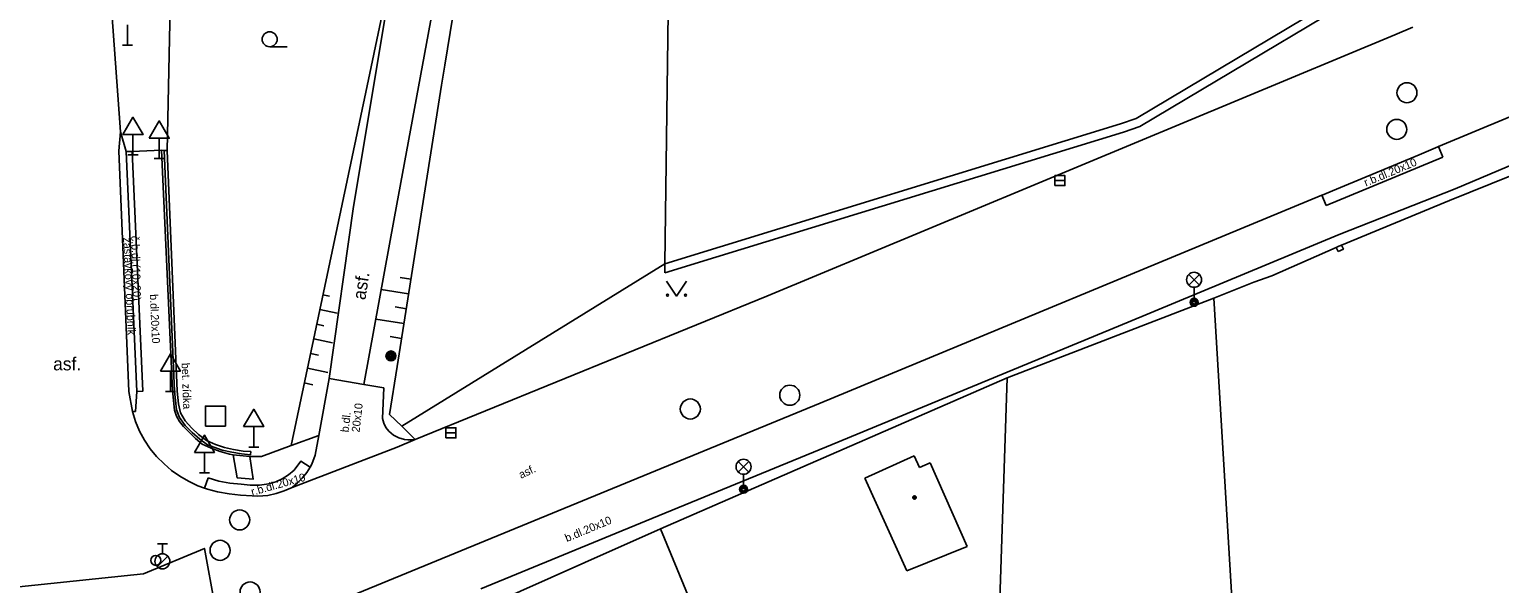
# Model space of a CAD drawing. Extents: x -598233 to -596890, y -1157848 to -1156431.
# Drawn here: x -598021.4 to -597948, y -1157077.3 to -1157049.6 of the extents above; entities that cross this region are included whole.
import ezdxf

# ---------------------------------------------------------------- set-up
doc = ezdxf.new("R2010")
doc.units = 0
for name, color, linetype in [('Level 10', 7, 'Continuous'), ('Level 11', 7, 'Continuous'), ('Level 15', 7, 'Continuous'), ('Level 24', 7, 'Continuous'), ('Level 25', 7, 'Continuous'), ('Level 26', 7, 'Continuous'), ('Level 27', 7, 'Continuous'), ('Level 28', 7, 'Continuous'), ('Level 33', 7, 'Continuous'), ('Level 34', 7, 'Continuous'), ('Level 36', 7, 'Continuous'), ('Level 39', 7, 'Continuous'), ('Level 40', 7, 'Continuous'), ('Level 5', 7, 'Continuous'), ('Level 7', 7, 'Continuous'), ('Level 8', 7, 'Continuous'), ('Vrstva 54', 7, 'Continuous'), ('Vrstva 60', 7, 'Continuous')]:
    doc.layers.add(name, color=color, linetype=linetype)

msp = doc.modelspace()

# ---------------------------------------------------------------- linework, layer by layer
at = {"layer": 'Level 10'}
for points in [[(-597997.82, -1157011.45), (-597999.15, -1157022.95), (-598000.01, -1157041.65), (-598003.21, -1157058.99)], [(-598017.85, -1157035.59), (-598017.6, -1157045.12), (-598016.9, -1157054.74)], [(-597953.22, -1157049.89), (-597984.6, -1157062.95)], [(-597952.31, -1157049.51), (-597953.22, -1157049.89)], [(-597944.1, -1157052.59), (-597951.04, -1157055.48), (-597951.07, -1157055.49)], [(-598016.97, -1157055.69), (-598016.9, -1157054.74)], [(-598016.47, -1157067.72), (-598016.97, -1157055.69)], [(-597951.07, -1157055.49), (-597952, -1157055.89), (-597955.94, -1157057.52)], [(-597956.86, -1157057.91), (-597981.94, -1157068.3)], [(-597955.94, -1157057.52), (-597956.84, -1157057.9), (-597956.86, -1157057.91)], [(-598006.47, -1157067.07), (-598005.25, -1157058.48)], [(-598003.21, -1157058.99), (-598004.74, -1157067.36)], [(-597984.6, -1157062.95), (-598002.17, -1157070.12)], [(-598006.98, -1157069.91), (-598006.47, -1157067.07)], [(-598004.74, -1157067.36), (-598003.73, -1157067.53)], [(-598003.73, -1157067.53), (-598003.81, -1157069.07)], [(-598016.29, -1157068.72), (-598016.47, -1157067.72)], [(-597981.94, -1157068.3), (-598005.96, -1157078.18)], [(-598016.29, -1157068.72), (-598016.14, -1157069.22)], [(-598003.63, -1157069.51), (-598003.74, -1157069.3), (-598003.81, -1157069.07)], [(-598015.69, -1157070.15), (-598015.94, -1157069.7), (-598016.14, -1157069.22)], [(-598007.16, -1157070.89), (-598006.98, -1157069.91)], [(-598003.63, -1157069.51), (-598003.48, -1157069.7)], [(-598003.48, -1157069.7), (-598003.25, -1157069.89)], [(-598002.71, -1157070.11), (-598002.99, -1157070.03), (-598003.25, -1157069.89)], [(-598014.72, -1157071.33), (-598015.09, -1157070.97), (-598015.41, -1157070.58), (-598015.69, -1157070.15)], [(-598002.71, -1157070.11), (-598002.53, -1157070.13)], [(-598002.17, -1157070.12), (-598002.35, -1157070.13), (-598002.53, -1157070.13)], [(-598013.49, -1157072.2), (-598013.93, -1157071.95), (-598014.34, -1157071.66), (-598014.72, -1157071.33)], [(-598007.16, -1157070.89), (-598007.33, -1157071.35), (-598007.42, -1157071.5), (-598007.58, -1157071.77)], [(-598007.58, -1157071.77), (-598007.81, -1157072.04), (-598008.05, -1157072.28), (-598008.32, -1157072.51)], [(-598013.49, -1157072.2), (-598013.03, -1157072.42)], [(-598012.69, -1157072.55), (-598013.03, -1157072.42)], [(-598012.05, -1157072.73), (-598012.55, -1157072.6), (-598012.69, -1157072.55)], [(-598010.31, -1157072.93), (-598010.89, -1157072.89), (-598011.47, -1157072.82), (-598012.05, -1157072.73)], [(-598008.32, -1157072.51), (-598008.71, -1157072.67), (-598009.12, -1157072.81), (-598009.53, -1157072.91)], [(-598009.79, -1157072.93), (-598010.05, -1157072.94), (-598010.31, -1157072.93)], [(-598009.79, -1157072.93), (-598009.53, -1157072.91)]]:
    msp.add_lwpolyline(points, dxfattribs=at)
at = {"layer": 'Level 11'}
for points in [[(-597989.69, -1157061.33), (-597966.92, -1157054.34), (-597966.15, -1157054.07), (-597951.92, -1157045.58), (-597952.39, -1157043.4)], [(-598005.25, -1157058.48), (-598003.01, -1157044.98)], [(-597951.4099, -1157045.8), (-597965.96, -1157054.48), (-597966.78, -1157054.76)], [(-597938.86, -1157052.79), (-597941.1, -1157053.74), (-597950.21, -1157057.59)], [(-598016.9, -1157054.74), (-598016.61, -1157055.73)], [(-597966.78, -1157054.76), (-597987.14, -1157061.01)], [(-598014.84, -1157055.66), (-598016.31, -1157055.72), (-598016.61, -1157055.73)], [(-598016.61, -1157055.73), (-598016.08, -1157067.71)], [(-598016.31, -1157055.72), (-598015.78, -1157067.7), (-598016.08, -1157067.71)], [(-598014.29, -1157067.66), (-598014.84, -1157055.66)], [(-598014.84, -1157055.66), (-598014.71, -1157055.68)], [(-598014.57, -1157055.67), (-598014.06, -1157067.7)], [(-597951.04, -1157055.48), (-597950.82, -1157056.01)], [(-597956.65, -1157058.42), (-597950.82, -1157056.01)], [(-597950.21, -1157057.59), (-597955.99, -1157059.87), (-597966.54, -1157064.25)], [(-597956.86, -1157057.91), (-597956.65, -1157058.42)], [(-597989.7, -1157061.79), (-597987.14, -1157061.01)], [(-597989.69, -1157061.33), (-598002.84, -1157069.44)], [(-597989.69, -1157061.33), (-597989.7, -1157061.79)], [(-597966.54, -1157064.25), (-597981.34, -1157070.37)], [(-598016.14, -1157068.72), (-598016.08, -1157067.71)], [(-598014.2, -1157068.65), (-598014.29, -1157067.66)], [(-598014.06, -1157067.7), (-598013.99, -1157068.33)], [(-598006.47, -1157067.07), (-598004.74, -1157067.36)], [(-598013.99, -1157068.33), (-598013.89, -1157068.78)], [(-598016.29, -1157068.72), (-598016.14, -1157068.72)], [(-598014.2, -1157068.65), (-598014.09, -1157068.94)], [(-598013.74, -1157069.46), (-598013.94, -1157069.22), (-598014.09, -1157068.94)], [(-598013.89, -1157068.78), (-598013.66, -1157069.18)], [(-598013.66, -1157069.18), (-598013.33, -1157069.54)], [(-598012.81, -1157070.34), (-598013.14, -1157070.07), (-598013.45, -1157069.77), (-598013.74, -1157069.46)], [(-598013.33, -1157069.54), (-598013, -1157069.87)], [(-598013, -1157069.87), (-598012.59, -1157070.16)], [(-598009.85, -1157070.96), (-598008.37, -1157070.42), (-598006.98, -1157069.91)], [(-598012.81, -1157070.34), (-598012.37, -1157070.55)], [(-598012.59, -1157070.16), (-598012.14, -1157070.36)], [(-598011.44, -1157070.85), (-598011.91, -1157070.72), (-598012.37, -1157070.55)], [(-598012.14, -1157070.36), (-598011.69, -1157070.52)], [(-598011.69, -1157070.52), (-598011.25, -1157070.62)], [(-598011.25, -1157070.62), (-598010.76, -1157070.69)], [(-598008.32, -1157072.51), (-598003.07, -1157070.5)], [(-598002.17, -1157070.12), (-598003.07, -1157070.5)], [(-597981.34, -1157070.37), (-597990.63, -1157074.17)], [(-598011.44, -1157070.85), (-598011.27, -1157070.88)], [(-598011.27, -1157070.88), (-598010.44, -1157070.97)], [(-598010.44, -1157070.97), (-598010.27, -1157072.1), (-598011.06, -1157072.03), (-598011.27, -1157070.88)], [(-598010.76, -1157070.69), (-598010.39, -1157070.71)], [(-598010.44, -1157070.97), (-598009.85, -1157070.96)], [(-598010.4, -1157070.88), (-598010.39, -1157070.71)], [(-598008.22, -1157071.65), (-598007.88, -1157071.19), (-598007.42, -1157071.5)], [(-598012.69, -1157072.55), (-598012.51, -1157072.02)], [(-598010.87, -1157072.35), (-598011.43, -1157072.3), (-598011.98, -1157072.19), (-598012.51, -1157072.02)], [(-598008.22, -1157071.65), (-598008.5, -1157071.88), (-598008.81, -1157072.08), (-598009.14, -1157072.23), (-598009.49, -1157072.33)], [(-598009.49, -1157072.33), (-598009.95, -1157072.39), (-598010.41, -1157072.39), (-598010.87, -1157072.35)], [(-597990.63, -1157074.17), (-597998.89, -1157077.58)], [(-597989.91, -1157074.57), (-597988.13, -1157078.89), (-597987.75, -1157100.84)]]:
    msp.add_lwpolyline(points, dxfattribs=at)
at = {"layer": 'Level 15'}
for points in [[(-598002.38, -1157062.1), (-598002.92, -1157062.02)], [(-598006.78, -1157062.88), (-598006.45, -1157062.95)], [(-598002.5, -1157062.84), (-598003.87, -1157062.62)], [(-598006.93, -1157063.62), (-598006.07, -1157063.8)], [(-598002.61, -1157063.58), (-598003.17, -1157063.49)], [(-598007.09, -1157064.35), (-598006.73, -1157064.43)], [(-598002.73, -1157064.32), (-598004.14, -1157064.1)], [(-598007.24, -1157065.08), (-598006.3, -1157065.28)], [(-598002.85, -1157065.06), (-598003.42, -1157064.97)], [(-598007.4, -1157065.82), (-598007, -1157065.9)], [(-598007.55, -1157066.55), (-598006.53, -1157066.77)], [(-598007.71, -1157067.29), (-598007.28, -1157067.38)]]:
    msp.add_lwpolyline(points, dxfattribs=at)
at = {"layer": 'Level 24'}
msp.add_lwpolyline([(-597956.05, -1157060.72), (-597956.14, -1157060.52), (-597956.01, -1157060.46), (-597955.88, -1157060.4), (-597955.79, -1157060.6), (-597956.05, -1157060.72)], dxfattribs=at)
at = {"layer": 'Level 25'}
for radius in [0.25, 0.2, 0.15, 0.1, 0.05]:
    msp.add_circle((-598003.38, -1157065.94), radius, dxfattribs=at)
at = {"layer": 'Level 26'}
msp.add_lwpolyline([(-598012.65, -1157069.44), (-598011.65, -1157069.44), (-598011.65, -1157068.44), (-598012.65, -1157068.44)], close=True, dxfattribs=at)
at = {"layer": 'Level 27'}
for p, q in [((-597970.2, -1157057.18), (-597969.7, -1157057.18)), ((-598000.63, -1157069.78), (-598000.13, -1157069.78))]:
    msp.add_line(p, q, dxfattribs=at)
for points in [[(-597970.2, -1157057.43), (-597969.7, -1157057.43), (-597969.7, -1157056.93), (-597970.2, -1157056.93)], [(-598000.63, -1157070.03), (-598000.13, -1157070.03), (-598000.13, -1157069.53), (-598000.63, -1157069.53)]]:
    msp.add_lwpolyline(points, close=True, dxfattribs=at)
for centre in [(-597952.61, -1157052.79), (-597953.12, -1157054.62), (-597983.45, -1157067.9), (-597988.42, -1157068.59), (-598010.94, -1157074.13), (-598011.92, -1157075.65), (-598010.42, -1157077.73)]:
    msp.add_circle(centre, 0.5, dxfattribs=at)
at = {"layer": 'Level 28'}
for p, q in [((-598015.05, -1157075.325), (-598014.55, -1157075.325)), ((-598014.8, -1157075.825), (-598014.8, -1157075.325)), ((-598015.058, -1157076.472), (-598014.528, -1157075.942))]:
    msp.add_line(p, q, dxfattribs=at)
for centre, radius in [((-598015.13, -1157076.15), 0.25), ((-598014.8, -1157076.2), 0.375)]:
    msp.add_circle(centre, radius, dxfattribs=at)
at = {"layer": 'Level 33'}
for p, q in [((-597963.515, -1157062.4), (-597962.985, -1157061.87)), ((-597963.515, -1157061.87), (-597962.985, -1157062.4)), ((-597963.25, -1157062.51), (-597963.25, -1157063.26)), ((-597986.025, -1157071.74), (-597985.495, -1157071.21)), ((-597986.025, -1157071.21), (-597985.495, -1157071.74)), ((-597985.76, -1157071.85), (-597985.76, -1157072.6))]:
    msp.add_line(p, q, dxfattribs=at)
for centre, radius in [((-597963.25, -1157062.135), 0.375), ((-597963.25, -1157063.26), 0.2), ((-597963.25, -1157063.26), 0.1445), ((-597963.25, -1157063.26), 0.0876), ((-597985.76, -1157071.475), 0.375), ((-597985.76, -1157072.6), 0.2), ((-597985.76, -1157072.6), 0.1445), ((-597985.76, -1157072.6), 0.0876)]:
    msp.add_circle(centre, radius, dxfattribs=at)
at = {"layer": 'Level 34'}
for p, q in [((-598016.54, -1157049.392), (-598016.54, -1157050.41)), ((-598016.79, -1157050.41), (-598016.29, -1157050.41)), ((-598016.27, -1157054.882), (-598016.27, -1157055.9)), ((-598014.96, -1157055.062), (-598014.96, -1157056.08)), ((-598016.52, -1157055.9), (-598016.02, -1157055.9)), ((-598015.21, -1157056.08), (-598014.71, -1157056.08)), ((-598014.4, -1157066.692), (-598014.4, -1157067.71)), ((-598014.65, -1157067.71), (-598014.15, -1157067.71)), ((-598010.24, -1157069.472), (-598010.24, -1157070.49)), ((-598010.49, -1157070.49), (-598009.99, -1157070.49)), ((-598012.7, -1157070.762), (-598012.7, -1157071.78)), ((-598012.95, -1157071.78), (-598012.45, -1157071.78))]:
    msp.add_line(p, q, dxfattribs=at)
for points in [[(-598016.77, -1157054.882), (-598015.77, -1157054.882), (-598016.27, -1157054.016)], [(-598015.46, -1157055.062), (-598014.46, -1157055.062), (-598014.96, -1157054.196)], [(-598014.9, -1157066.692), (-598013.9, -1157066.692), (-598014.4, -1157065.826)], [(-598010.74, -1157069.472), (-598009.74, -1157069.472), (-598010.24, -1157068.606)], [(-598013.2, -1157070.762), (-598012.2, -1157070.762), (-598012.7, -1157069.896)]]:
    msp.add_lwpolyline(points, close=True, dxfattribs=at)
at = {"layer": 'Level 36'}
msp.add_line((-598009.44, -1157050.495), (-598008.565, -1157050.495), dxfattribs=at)
msp.add_lwpolyline([(-597989.61, -1157062.2), (-597989.11, -1157062.95), (-597988.61, -1157062.2)], dxfattribs=at)
for centre, radius in [((-598009.4401, -1157050.1199), 0.375), ((-597989.5602, -1157062.8998), 0.05), ((-597988.6608, -1157062.8998), 0.05)]:
    msp.add_circle(centre, radius, dxfattribs=at)
at = {"layer": 'Level 39'}
for radius in [0.09, 0.0398]:
    msp.add_circle((-597977.2199, -1157073.01), radius, dxfattribs=at)
at = {"layer": 'Level 5'}
for points in [[(-597979.7, -1157072.04), (-597977.24, -1157070.93)], [(-597977.24, -1157070.93), (-597976.9699, -1157071.52)], [(-597976.9699, -1157071.52), (-597976.43, -1157071.28)], [(-597976.43, -1157071.28), (-597974.59, -1157075.46)], [(-597977.6, -1157076.68), (-597979.7, -1157072.04)], [(-597974.59, -1157075.46), (-597977.6, -1157076.68)]]:
    msp.add_lwpolyline(points, dxfattribs=at)
at = {"layer": 'Level 7'}
for points in [[(-597989.18, -1157022.45), (-597989.69, -1157061.33)], [(-598000.69, -1157051.42), (-597999.9099, -1157046.6), (-597999.2199, -1157041.7199), (-597998.78, -1157027.94)], [(-598014.21, -1157038.92), (-598014.57, -1157055.67)], [(-598003.01, -1157044.98), (-598004.64, -1157052.77), (-598008.37, -1157070.42)], [(-598000.69, -1157051.42), (-598000.85, -1157052.4099)], [(-598003.45, -1157068.87), (-598003.07, -1157066.4699), (-598000.85, -1157052.4099)], [(-597941.1, -1157054.4), (-597950.48, -1157058.17)], [(-598014.71, -1157055.68), (-598014.57, -1157055.67)], [(-598014.19, -1157067.7), (-598014.71, -1157055.68)], [(-597950.48, -1157058.17), (-597955.88, -1157060.4)], [(-597956.14, -1157060.52), (-597959.37, -1157061.94)], [(-597959.37, -1157061.94), (-597960.26, -1157062.25)], [(-597962.26, -1157063.06), (-597972.59, -1157067.04), (-597989.91, -1157074.57)], [(-597961.56, -1157101), (-597961.3, -1157079.14), (-597962.26, -1157063.06)], [(-598014.19, -1157067.7), (-598014.1, -1157068.63)], [(-597972.95, -1157078.11), (-597972.59, -1157067.04)], [(-598014.1, -1157068.63), (-598013.95, -1157069.01)], [(-598013.95, -1157069.01), (-598013.67, -1157069.41)], [(-598003.45, -1157068.87), (-598002.84, -1157069.44)], [(-598013.67, -1157069.41), (-598013.32, -1157069.77)], [(-598013.32, -1157069.77), (-598012.93, -1157070.1)], [(-598002.84, -1157069.44), (-598002.17, -1157070.12)], [(-598012.93, -1157070.1), (-598012.55, -1157070.38)], [(-598012.55, -1157070.38), (-598011.82, -1157070.64)], [(-598011.82, -1157070.64), (-598011.33, -1157070.74)], [(-598011.33, -1157070.74), (-598010.85, -1157070.83)], [(-598010.85, -1157070.83), (-598010.4, -1157070.88)], [(-597991.74, -1157075.39), (-597989.91, -1157074.57)], [(-597991.74, -1157075.39), (-597992.01, -1157075.51), (-598000.27, -1157079.19), (-598007.15, -1157082.25)]]:
    msp.add_lwpolyline(points, dxfattribs=at)
at = {"layer": 'Level 8'}
msp.add_lwpolyline([(-597962.26, -1157063.06), (-597960.26, -1157062.25)], dxfattribs=at)
at = {"layer": 'Vrstva 54'}
for p, q in [((-598015.75, -1157076.83), (-598012.7, -1157075.55)), ((-598012.7, -1157075.55), (-598012.18, -1157078.39)), ((-598022.29, -1157077.5), (-598016.22, -1157076.88)), ((-598016.22, -1157076.88), (-598015.75, -1157076.83))]:
    msp.add_line(p, q, dxfattribs=at)
at = {"layer": 'Vrstva 60'}
for points in [[(-598022.29, -1157077.5), (-598016.22, -1157076.88), (-598015.75, -1157076.83), (-598012.7, -1157075.55), (-598012.18, -1157078.39), (-598007.76, -1157081.79), (-598007.38, -1157082.09), (-598006.64, -1157087.09), (-598004.37, -1157102.53), (-597989.03, -1157132.27), (-597984.94, -1157135.42)], [(-597984.94, -1157135.42), (-597989.03, -1157132.27), (-598004.37, -1157102.53), (-598006.64, -1157087.09), (-598007.38, -1157082.09), (-598007.76, -1157081.79), (-598012.18, -1157078.39), (-598012.7, -1157075.55), (-598015.75, -1157076.83), (-598016.22, -1157076.88), (-598022.29, -1157077.5)]]:
    msp.add_lwpolyline(points, dxfattribs=at)

# ---------------------------------------------------------------- texts
at = {"layer": 'Level 40'}
for s, height, rotation, p in [('r.b.dl.20x10', 0.400002, 22.603497, (-597954.66, -1157057.48)), ('zastávkový obrubník', 0.400002, 272.624219, (-598016.76, -1157060.03)), ('č.b.dl.(10x20)', 0.399996, 271.719242, (-598016.36, -1157059.94)), ('asf.', 0.65, 81.249506, (-598004.66, -1157063.17)), ('b.dl.20x10', 0.4, 272.624219, (-598015.43, -1157062.86)), ('bet. zídka', 0.4, 272, (-598013.84, -1157066.29)), ('20x10', 0.4, 83.537014, (-598004.95, -1157069.77)), ('b.dl.', 0.4, 83.537014, (-598005.5, -1157069.77)), ('r.b.dl.20x10', 0.400002, 15.859367, (-598010.31, -1157072.93)), ('asf.', 0.4, 25.219528, (-597996.88, -1157072.08)), ('b.dl.20x10', 0.4, 22.595322, (-597994.59, -1157075.24))]:
    msp.add_text(s, height=height, rotation=rotation, dxfattribs=at).set_placement(p)
msp.add_text('asf.', height=0.65, dxfattribs=at).set_placement((-598020.26, -1157066.6599))

doc.saveas('drawing.dxf')
